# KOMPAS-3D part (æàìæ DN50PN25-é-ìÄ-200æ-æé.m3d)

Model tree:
1. Объединить компоненты:1  (labels: СЕНС DN50PN25-В-НО-200С)
2. Эскиз:1
3. Операция выдавливания:1
     Расстояние 1 = 14
4. Фаска:1
     Угол = 45; Длина 1 = 2; Длина 2 = 2

Referenced files in D:\Савин\!СЕНСОР\3D для заказчика\!Новый перечень\СЕНС\7. СЕНС-В-НО-200С\DN50\: СЕНС DN50PN25-В-НО-200С.a3d
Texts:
  СЕНС DN50PN25-В-НО-200С-СВ
  ООО НПП Сенсор
  СЕНС DN50PN25-В-НО-200С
